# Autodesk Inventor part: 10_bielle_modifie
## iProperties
Created: 2002-11
Part Number: 10_bielle_modifie
Material: Par défaut
Document SubType Name: Modélisation
Designer: poste-2
Control State: 0
Master: False
Checked Out: False
Shininess: 24.0
Length Units: 11269
Angle Units: 11279
Time Units: 11290
Mass Units: 11283
Length Display Precision: 3
Angle Display Precision: 2
Compacted: True
Density: 0.0
Volumn: 0.0
Area: 0.0
PropertySet Name: Model Information
Author: poste-2
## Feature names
1. Révolution1 [Revolution]
2. Scission1
3. Scission2
4. Extrusion1
